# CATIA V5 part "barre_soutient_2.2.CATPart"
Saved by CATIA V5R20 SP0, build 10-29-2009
Part number: barre_soutient_2.2
Bounding box of the stored display mesh (mm): x 505.778 to 2805.778, y -686.148 to -616.167, z -686.975 to -617.207
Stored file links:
  C:\Users\Mike-7\Desktop\MMS_GR3\bfoltzer\CFAO_bfoltzer\barre_soutient_2.2.CATPart
  D:\ecole\thinkmotion\Eolienne.CATProduct
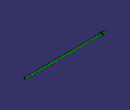
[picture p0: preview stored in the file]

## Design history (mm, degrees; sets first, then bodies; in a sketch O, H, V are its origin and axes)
Set1
  Plane1 "plan dessin": linked copy from another document
  Point1: linked copy from another document
  Point2: linked copy from another document
  Line1 "axe de rotation": linked copy from another document
  Point3: linked copy from another document
  Point4: linked copy from another document
Body1 (main body)
  Sketch1 on Plane1, origin (0, -2074.8788, 1309.1035), H (1, 0, 0), V (0, -0.5875, 0.8092)
    point P1 (505.7782, -2403.4823)
    line L1 (505.7782, -2403.4823) -> (2805.7782, -2403.4823)
    line L2 (2805.7782, -2403.4823) -> (2805.7782, -2423.4823)
    line L3 (2805.7782, -2423.4823) -> (505.7782, -2423.4823)
    line L4 (505.7782, -2423.4823) -> (505.7782, -2403.4823)
    point P3 (2805.7782, -2423.4823)
    reference projected point E1 (505.7782, -2403.4823) from Point1
    reference projected point E2 (2805.7782, -2423.4823) from Point2
    horizontal: L1 H, L3 H
    vertical: L2 V, L4 V
    coincidence: P1 E1, P3 E2
  Shaft1: profile Sketch1, axis Line1, angle 360
  Sketch2 on Plane1, origin (0, -2074.8788, 1309.1035), H (1, 0, 0), V (0, -0.5875, 0.8092)
    line L1 (625.7782, -2458.4823) -> (605.7782, -2458.4823)
    line L2 (605.7782, -2458.4823) -> (605.7782, -2443.4823)
    line L3 (605.7782, -2443.4823) -> (625.7782, -2443.4823)
    line L4 (625.7782, -2443.4823) -> (625.7782, -2458.4823)
    point P2 (605.7782, -2458.4823)
    point P4 (625.7782, -2443.4823)
    reference projected point E1 (625.7782, -2443.4823) from Point3
    reference projected point E2 (605.7782, -2458.4823) from Point4
    horizontal: L1 H, L3 H
    vertical: L2 V, L4 V
    coincidence: P4 E1, P2 E2
  Shaft2: profile Sketch2, axis Line1, angle 360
